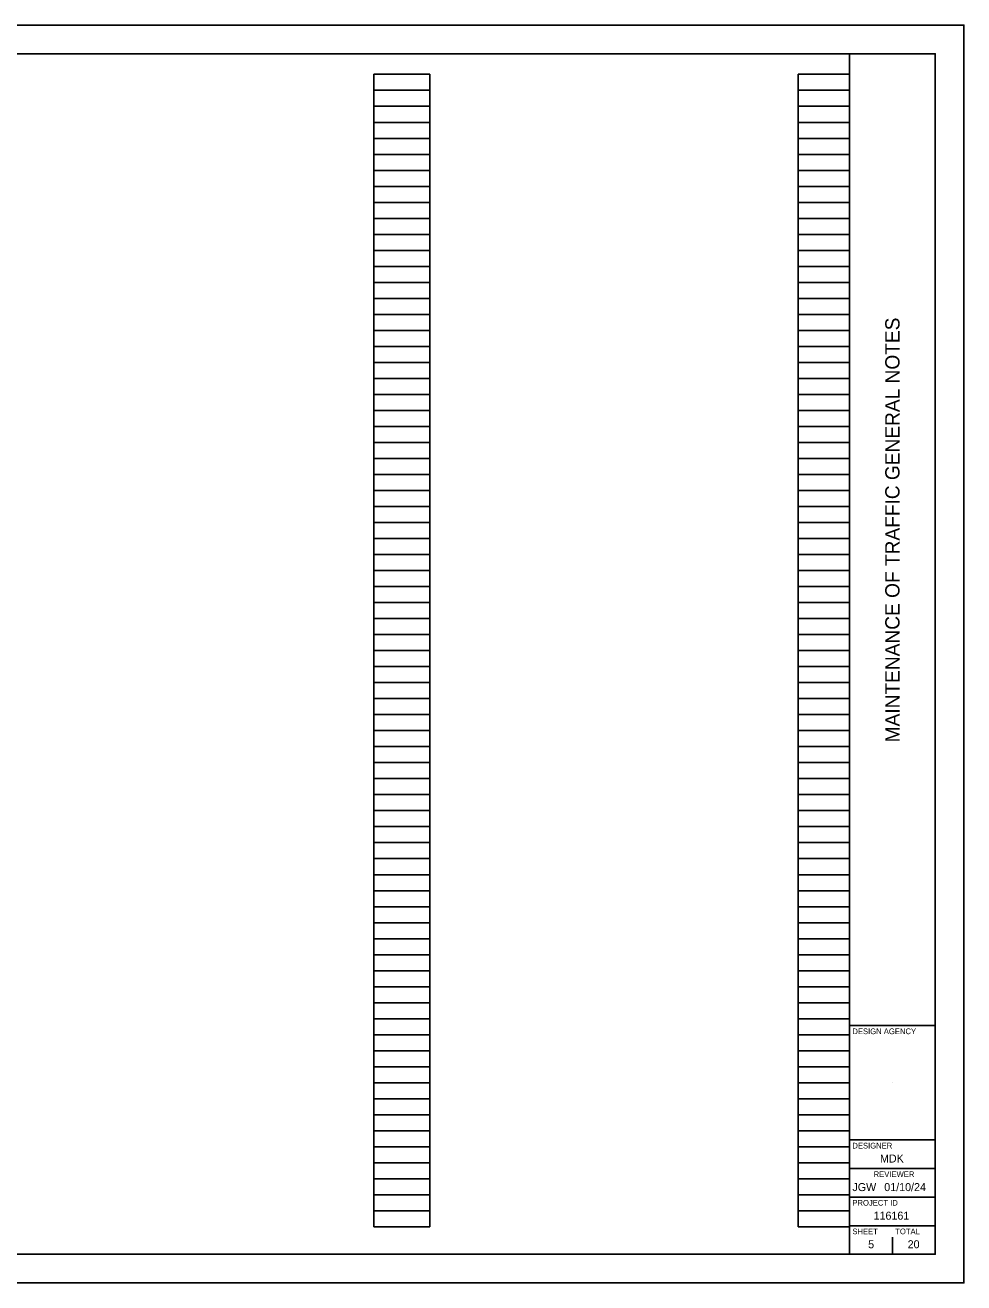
# Model space of a CAD drawing. Extents: x 0 to 34, y 0 to 22.
# Drawn here: x 17.58 to 34, y 0 to 22 of the extents above; entities that cross this region are included whole.
import ezdxf

# ---------------------------------------------------------------- set-up
doc = ezdxf.new("R2010")
doc.units = 0
for name, color, linetype in [('SH_Border', 7, 'Continuous'), ('SH_Cut_Line', 7, 'Continuous'), ('SH_Data', 7, 'Continuous')]:
    doc.layers.add(name, color=color, linetype=linetype)

msp = doc.modelspace()

# ---------------------------------------------------------------- linework, layer by layer
at = {"layer": 'SH_Border'}
for p, q in [((32, 0.5), (32, 21.5)), ((32, 4.5), (33.5, 4.5)), ((32, 2.5), (33.5, 2.5)), ((32, 2), (33.5, 2)), ((32, 1.5), (33.5, 1.5)), ((32, 1), (33.5, 1))]:
    msp.add_line(p, q, dxfattribs=at)
msp.add_lwpolyline([(1.5, 21.5), (33.5, 21.5), (33.5, 0.5), (1.5, 0.5)], close=True, dxfattribs=at)
at = {"layer": 'SH_Cut_Line'}
msp.add_lwpolyline([(0, 0), (34, 0), (34, 22), (0, 22)], close=True, dxfattribs=at)
at = {"layer": 'SH_Data'}
for p, q in [((23.68, 0.98), (23.68, 21.14)), ((23.68, 21.14), (24.66, 21.14)), ((24.66, 0.98), (24.66, 21.14)), ((31.1, 0.98), (31.1, 21.14)), ((31.1, 21.14), (32, 21.14)), ((32, 0.98), (32, 21.14)), ((23.68, 20.86), (24.66, 20.86)), ((31.1, 20.86), (32, 20.86)), ((23.68, 20.58), (24.66, 20.58)), ((31.1, 20.58), (32, 20.58)), ((23.68, 20.3), (24.66, 20.3)), ((31.1, 20.3), (32, 20.3)), ((23.68, 20.02), (24.66, 20.02)), ((31.1, 20.02), (32, 20.02)), ((23.68, 19.74), (24.66, 19.74)), ((31.1, 19.74), (32, 19.74)), ((23.68, 19.46), (24.66, 19.46)), ((31.1, 19.46), (32, 19.46)), ((23.68, 19.18), (24.66, 19.18)), ((31.1, 19.18), (32, 19.18)), ((23.68, 18.9), (24.66, 18.9)), ((31.1, 18.9), (32, 18.9)), ((23.68, 18.62), (24.66, 18.62)), ((31.1, 18.62), (32, 18.62)), ((23.68, 18.34), (24.66, 18.34)), ((31.1, 18.34), (32, 18.34)), ((23.68, 18.06), (24.66, 18.06)), ((31.1, 18.06), (32, 18.06)), ((23.68, 17.78), (24.66, 17.78)), ((31.1, 17.78), (32, 17.78)), ((23.68, 17.5), (24.66, 17.5)), ((31.1, 17.5), (32, 17.5)), ((23.68, 17.22), (24.66, 17.22)), ((31.1, 17.22), (32, 17.22)), ((23.68, 16.94), (24.66, 16.94)), ((31.1, 16.94), (32, 16.94)), ((23.68, 16.66), (24.66, 16.66)), ((31.1, 16.66), (32, 16.66)), ((23.68, 16.38), (24.66, 16.38)), ((31.1, 16.38), (32, 16.38)), ((23.68, 16.1), (24.66, 16.1)), ((31.1, 16.1), (32, 16.1)), ((23.68, 15.82), (24.66, 15.82)), ((31.1, 15.82), (32, 15.82)), ((23.68, 15.54), (24.66, 15.54)), ((31.1, 15.54), (32, 15.54)), ((23.68, 15.26), (24.66, 15.26)), ((31.1, 15.26), (32, 15.26)), ((23.68, 14.98), (24.66, 14.98)), ((31.1, 14.98), (32, 14.98)), ((23.68, 14.7), (24.66, 14.7)), ((31.1, 14.7), (32, 14.7)), ((23.68, 14.42), (24.66, 14.42)), ((31.1, 14.42), (32, 14.42)), ((23.68, 14.14), (24.66, 14.14)), ((31.1, 14.14), (32, 14.14)), ((23.68, 13.86), (24.66, 13.86)), ((31.1, 13.86), (32, 13.86)), ((23.68, 13.58), (24.66, 13.58)), ((31.1, 13.58), (32, 13.58)), ((23.68, 13.3), (24.66, 13.3)), ((31.1, 13.3), (32, 13.3)), ((23.68, 13.02), (24.66, 13.02)), ((31.1, 13.02), (32, 13.02)), ((23.68, 12.74), (24.66, 12.74)), ((31.1, 12.74), (32, 12.74)), ((23.68, 12.46), (24.66, 12.46)), ((31.1, 12.46), (32, 12.46)), ((23.68, 12.18), (24.66, 12.18)), ((31.1, 12.18), (32, 12.18)), ((23.68, 11.9), (24.66, 11.9)), ((31.1, 11.9), (32, 11.9)), ((23.68, 11.62), (24.66, 11.62)), ((31.1, 11.62), (32, 11.62)), ((23.68, 11.34), (24.66, 11.34)), ((31.1, 11.34), (32, 11.34)), ((23.68, 11.06), (24.66, 11.06)), ((31.1, 11.06), (32, 11.06)), ((23.68, 10.78), (24.66, 10.78)), ((31.1, 10.78), (32, 10.78)), ((23.68, 10.5), (24.66, 10.5)), ((31.1, 10.5), (32, 10.5)), ((23.68, 10.22), (24.66, 10.22)), ((31.1, 10.22), (32, 10.22)), ((23.68, 9.94), (24.66, 9.94)), ((31.1, 9.94), (32, 9.94)), ((23.68, 9.66), (24.66, 9.66)), ((31.1, 9.66), (32, 9.66)), ((23.68, 9.38), (24.66, 9.38)), ((31.1, 9.38), (32, 9.38)), ((23.68, 9.1), (24.66, 9.1)), ((31.1, 9.1), (32, 9.1)), ((23.68, 8.82), (24.66, 8.82)), ((31.1, 8.82), (32, 8.82)), ((23.68, 8.54), (24.66, 8.54)), ((31.1, 8.54), (32, 8.54)), ((23.68, 8.26), (24.66, 8.26)), ((31.1, 8.26), (32, 8.26)), ((23.68, 7.98), (24.66, 7.98)), ((31.1, 7.98), (32, 7.98)), ((23.68, 7.7), (24.66, 7.7)), ((31.1, 7.7), (32, 7.7)), ((23.68, 7.42), (24.66, 7.42)), ((31.1, 7.42), (32, 7.42)), ((23.68, 7.14), (24.66, 7.14)), ((31.1, 7.14), (32, 7.14)), ((23.68, 6.86), (24.66, 6.86)), ((31.1, 6.86), (32, 6.86)), ((23.68, 6.58), (24.66, 6.58)), ((31.1, 6.58), (32, 6.58)), ((23.68, 6.3), (24.66, 6.3)), ((31.1, 6.3), (32, 6.3)), ((23.68, 6.02), (24.66, 6.02)), ((31.1, 6.02), (32, 6.02)), ((23.68, 5.74), (24.66, 5.74)), ((31.1, 5.74), (32, 5.74)), ((23.68, 5.46), (24.66, 5.46)), ((31.1, 5.46), (32, 5.46)), ((23.68, 5.18), (24.66, 5.18)), ((31.1, 5.18), (32, 5.18)), ((23.68, 4.9), (24.66, 4.9)), ((31.1, 4.9), (32, 4.9)), ((23.68, 4.62), (24.66, 4.62)), ((31.1, 4.62), (32, 4.62)), ((23.68, 4.34), (24.66, 4.34)), ((31.1, 4.34), (32, 4.34)), ((23.68, 4.06), (24.66, 4.06)), ((31.1, 4.06), (32, 4.06)), ((23.68, 3.78), (24.66, 3.78)), ((31.1, 3.78), (32, 3.78)), ((23.68, 3.5), (24.66, 3.5)), ((31.1, 3.5), (32, 3.5)), ((32.75, 3.5), (32.75, 3.5)), ((23.68, 3.22), (24.66, 3.22)), ((31.1, 3.22), (32, 3.22)), ((23.68, 2.94), (24.66, 2.94)), ((31.1, 2.94), (32, 2.94)), ((23.68, 2.66), (24.66, 2.66)), ((31.1, 2.66), (32, 2.66)), ((23.68, 2.38), (24.66, 2.38)), ((31.1, 2.38), (32, 2.38)), ((23.68, 2.1), (24.66, 2.1)), ((31.1, 2.1), (32, 2.1)), ((23.68, 1.82), (24.66, 1.82)), ((31.1, 1.82), (32, 1.82)), ((23.68, 1.54), (24.66, 1.54)), ((31.1, 1.54), (32, 1.54)), ((23.68, 1.26), (24.66, 1.26)), ((31.1, 1.26), (32, 1.26)), ((23.68, 0.98), (24.66, 0.98)), ((31.1, 0.98), (32, 0.98)), ((32.375, 0.675), (32.375, 0.675)), ((32.75, 0.5), (32.75, 0.8))]:
    msp.add_line(p, q, dxfattribs=at)

# ---------------------------------------------------------------- texts
msp.add_text('MAINTENANCE OF TRAFFIC GENERAL NOTES', height=0.25, rotation=90, dxfattribs=at).set_placement((32.875, 9.455))
for s, height, p in [('DESIGN AGENCY', 0.1, (32.05, 4.35)), ('DESIGNER', 0.1, (32.05, 2.35)), ('MDK', 0.14, (32.533, 2.105)), ('REVIEWER', 0.1, (32.422, 1.85)), ('JGW', 0.14, (32.051, 1.605)), ('01/10/24', 0.14, (32.608, 1.605)), ('PROJECT ID', 0.1, (32.05, 1.35)), ('116161', 0.14, (32.421, 1.105)), ('SHEET', 0.1, (32.05, 0.85)), ('TOTAL', 0.1, (32.8, 0.85)), ('5', 0.14, (32.326, 0.605)), ('20', 0.14, (33.017, 0.605))]:
    msp.add_text(s, height=height, dxfattribs=at).set_placement(p)

doc.saveas('drawing.dxf')
